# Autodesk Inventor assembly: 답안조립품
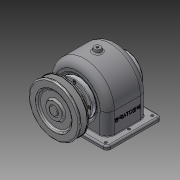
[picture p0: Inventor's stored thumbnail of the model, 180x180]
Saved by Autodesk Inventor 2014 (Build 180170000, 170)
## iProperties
Created: 2015-09
Part Number: 답안조립품
Document SubType Name: Assembly
Designer: Administrator
Author: Administrator
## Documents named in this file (14)
- C:\Users\Administrator\Desktop\450907V1046\답안조립품.iam
- C:\Users\Administrator\Desktop\450907V1046\1-본체.ipt
- C:\Users\Administrator\Desktop\450907V1046\V-벨트풀리.ipt
- C:\Users\Administrator\Desktop\450907V1046\뒤커버.ipt
- C:\Users\Administrator\Desktop\450907V1046\멈춤나사 - M4x10.ipt
- C:\Users\Administrator\Desktop\450907V1046\베어링 6203.ipt
- C:\Users\Administrator\Desktop\450907V1046\볼트 M3 x 8.ipt
- C:\Users\Administrator\Desktop\450907V1046\볼트 M3 x 10.ipt
- C:\Users\Administrator\Desktop\450907V1046\스퍼기어.ipt
- C:\Users\Administrator\Desktop\450907V1046\앞커버.ipt
- C:\Users\Administrator\Desktop\450907V1046\오일 실 17 32 8.ipt
- C:\Users\Administrator\Desktop\450907V1046\축.ipt
- C:\Users\Administrator\Desktop\450907V1046\키 - 5 x 5 x 18.ipt
- C:\Users\Administrator\Desktop\450907V1046\키 - 6 x 6 x 22.ipt
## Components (10 placed, 4 different names)
1. 1-본체:1
2. V-벨트풀리:1
3. ISO 4762 M3 x 8:1
4. ISO 4762 M3 x 10:1
5. ISO 4762 M3 x 10:2
6. ISO 4762 M3 x 10:3
7. ISO 4762 M3 x 10:4
8. ISO 4762 M3 x 8:2
9. ISO 4762 M3 x 8:3
10. ISO 4762 M3 x 8:4
